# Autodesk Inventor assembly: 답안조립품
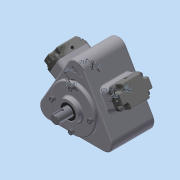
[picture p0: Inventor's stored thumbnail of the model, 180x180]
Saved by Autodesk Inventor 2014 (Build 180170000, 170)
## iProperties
Created: 2015-06
Part Number: 답안조립품
Document SubType Name: Assembly
Designer: MYHOME
Mass: 5318.58 g
Surface Area: 2414.92 cm^2
Volume: 1564.62 cm^3
Density: 3.39928 g/cm^3
Author: MYHOME
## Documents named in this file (20)
- C:\Documents and Settings\MYHOME\바탕 화면\350605V1037\답안조립품.iam
- C:\Documents and Settings\MYHOME\바탕 화면\350605V1037\본체.ipt
- C:\Documents and Settings\MYHOME\바탕 화면\350605V1037\헤더커버.ipt
- 헤더커버.ipt
- C:\Documents and Settings\MYHOME\바탕 화면\350605V1037\부시.ipt
- C:\Documents and Settings\MYHOME\바탕 화면\350605V1037\베어링 NA 4904.ipt
- 베어링 NA 4904.ipt
- C:\Documents and Settings\MYHOME\바탕 화면\350605V1037\편심축.ipt
- C:\Documents and Settings\MYHOME\바탕 화면\350605V1037\앞커버.ipt
- C:\Documents and Settings\MYHOME\바탕 화면\350605V1037\오일실.ipt
- 오일실.ipt
- C:\Documents and Settings\MYHOME\바탕 화면\350605V1037\M6x0.7x20.ipt
- M6x0.7x20.ipt
- C:\Documents and Settings\MYHOME\바탕 화면\350605V1037\슬라이드.ipt
- C:\Documents and Settings\MYHOME\바탕 화면\350605V1037\M4x0.5x16.ipt
- M4x0.5x16.ipt
- C:\Documents and Settings\MYHOME\바탕 화면\350605V1037\8-스프링.ipt
- C:\Documents and Settings\MYHOME\바탕 화면\350605V1037\9-스프링.ipt
- C:\Documents and Settings\MYHOME\바탕 화면\350605V1037\10-스프링.ipt
- C:\Documents and Settings\MYHOME\바탕 화면\350605V1037\11-스프링.ipt
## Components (18 placed, 7 different names)
1. 헤더커버:1
2. 헤더커버:2
3. M4x0.5x16:1
4. M4x0.5x16:2
5. M4x0.5x16:3
6. M4x0.5x16:4
7. M4x0.5x16:5
8. M4x0.5x16:6
9. M4x0.5x16:7
10. M4x0.5x16:8
11. 8-스프링:1
12. 9-스프링:1
13. 10-스프링:1
14. 11-스프링:1
15. M6x0.7x20:1
16. M6x0.7x20:2
17. M6x0.7x20:3
18. M6x0.7x20:4
